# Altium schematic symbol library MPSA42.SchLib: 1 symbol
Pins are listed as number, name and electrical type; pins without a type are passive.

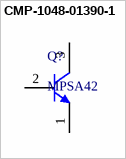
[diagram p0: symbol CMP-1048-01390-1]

## CMP-1048-01390-1
designator Q?, comment MPSA42
High Voltage Transistor, NPN Silicon, 3-Pin TO-92, Bulk Box; Manufacturer: On Semiconductor; fT Min (MHz): 50; Note1: 0; IC Continuous (A): 0.5
footprint ONSC-TO-92-3-29-11 (TO, 3-Leads, Body Dia 4.7mm, Pitch 1.27mm)
pins: 1 E, 2 B, 3 C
